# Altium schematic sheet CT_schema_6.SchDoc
size 300 x 247 mm
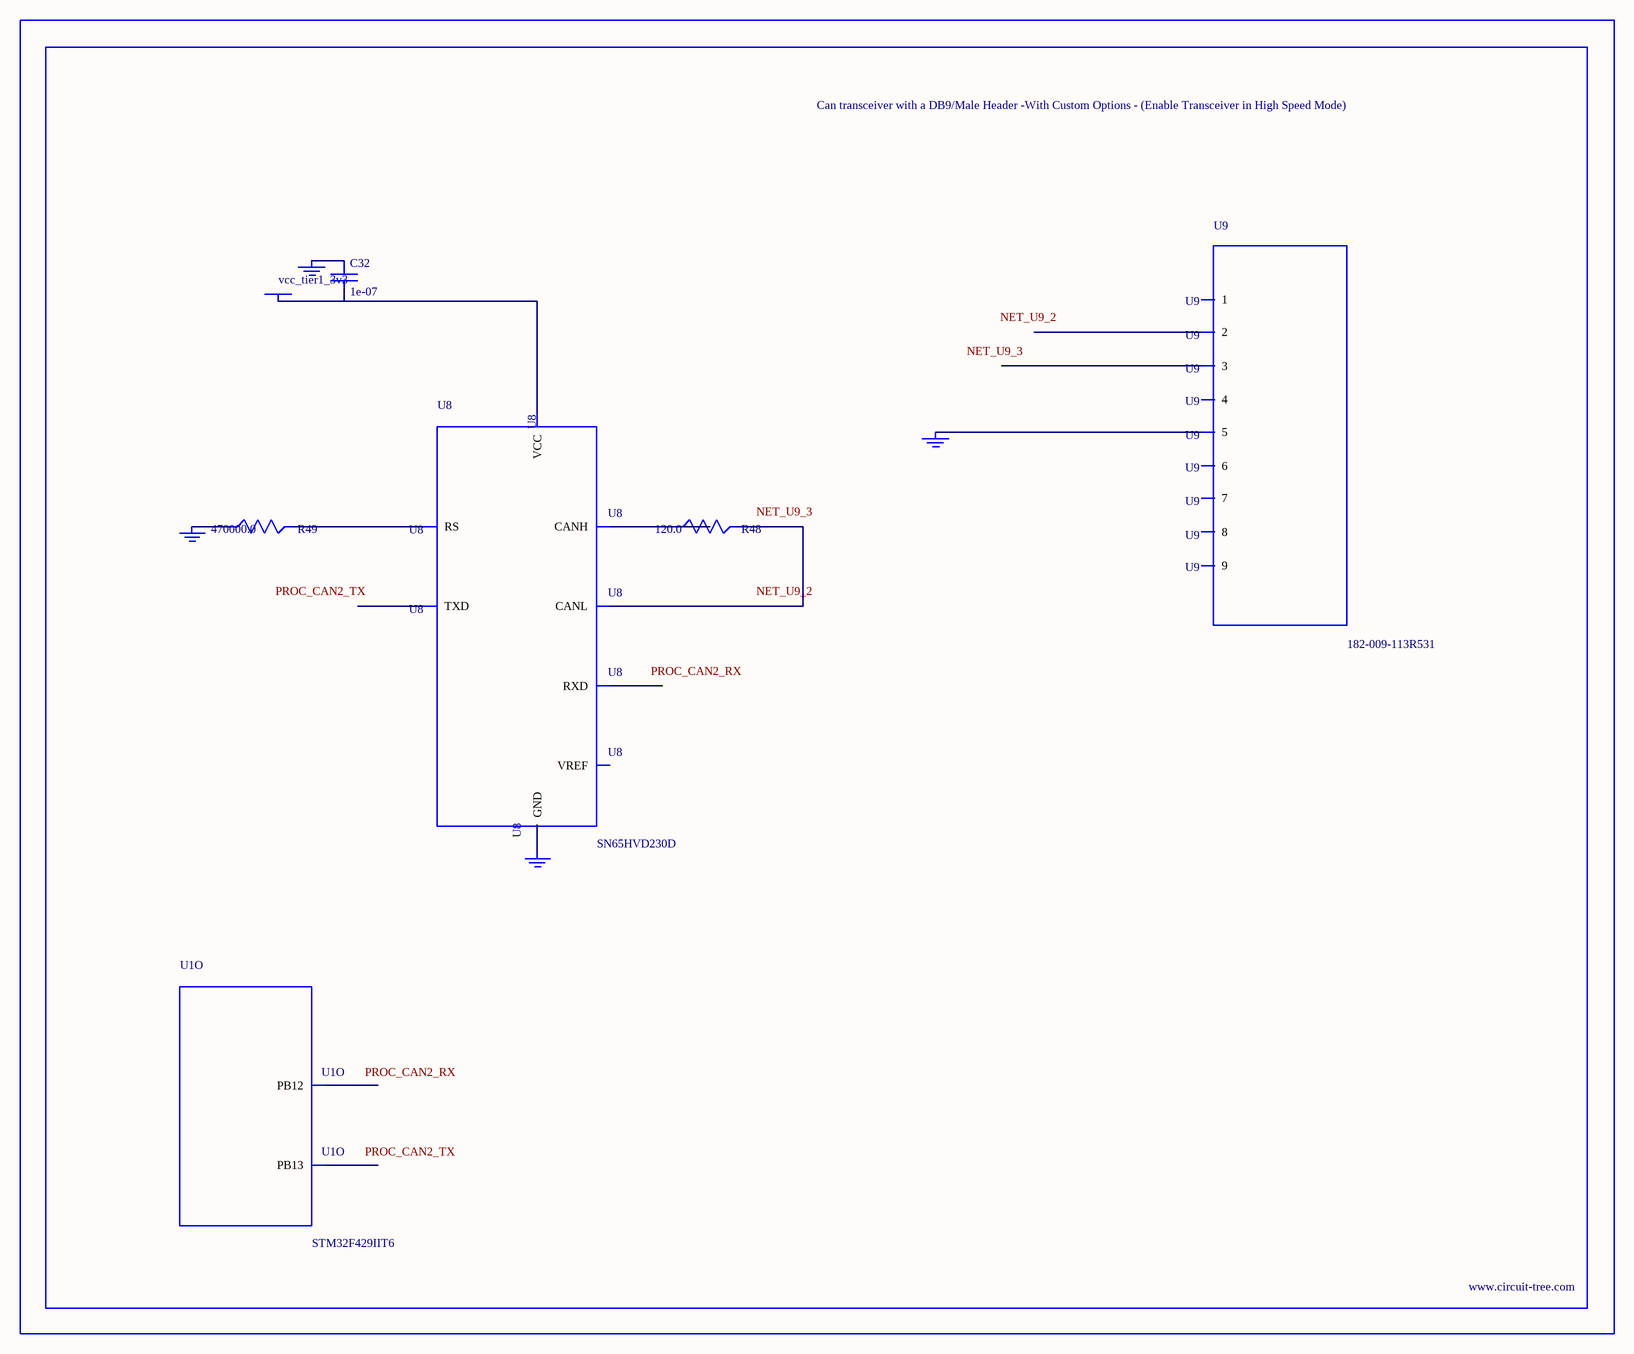
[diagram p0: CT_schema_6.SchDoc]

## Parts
BORDER5  (no value)
C32  1e-07  [C0402]
GND_INSTANCE_5_0  (no value)
GND_INSTANCE_5_1  (no value)
GND_INSTANCE_5_2  (no value)
GND_INSTANCE_5_3  (no value)
POWER_INSTANCE_5_0  vcc_tier1_3v3
R48  120.0  [R0603]
R49  470000.0  [R0603]
U1  STM32F429IIT6  [LQFP176]  (part O of 15)
U8  SN65HVD230D  [SOIC-8]
U9  182-009-113R531  [182-009-MALE]

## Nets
NetC32_1: C32.1 GND_INSTANCE_5_0.0(GND)
NetC32_2: C32.2 POWER_INSTANCE_5_0.0(PWR) U8.3(VCC)
NetGND_INSTANCE_5_1_0: GND_INSTANCE_5_1.0(GND) R49.1
NetGND_INSTANCE_5_2_0: GND_INSTANCE_5_2.0(GND) U8.2(GND)
NetGND_INSTANCE_5_3_0: GND_INSTANCE_5_3.0(GND) U9.5
NetR48_1: R48.1 U8.7(CANH)
NetR48_2: R48.2 U8.6(CANL)
NetR49_2: R49.2 U8.8(RS)

Not connected (* = marked no-connect by the designer): U1 92(PB12) 93(PB13); U8 1(TXD) 4(RXD) 5(VREF); U9 1 2 3 4 6 7 8 9

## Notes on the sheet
- Labels drawn without touching a wire or pin: NET_U9_2, NET_U9_3, PROC_CAN2_RX, PROC_CAN2_TX

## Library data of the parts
BORDER5 = BORDER_PAGE5
C32 = C0402C104K3RACTU
GND_INSTANCE_5_0-GND_INSTANCE_5_3 = GND
POWER_INSTANCE_5_0 = PWR
R48 = RC0603JR-07120RL
R49 = RC0603JR-07470KL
